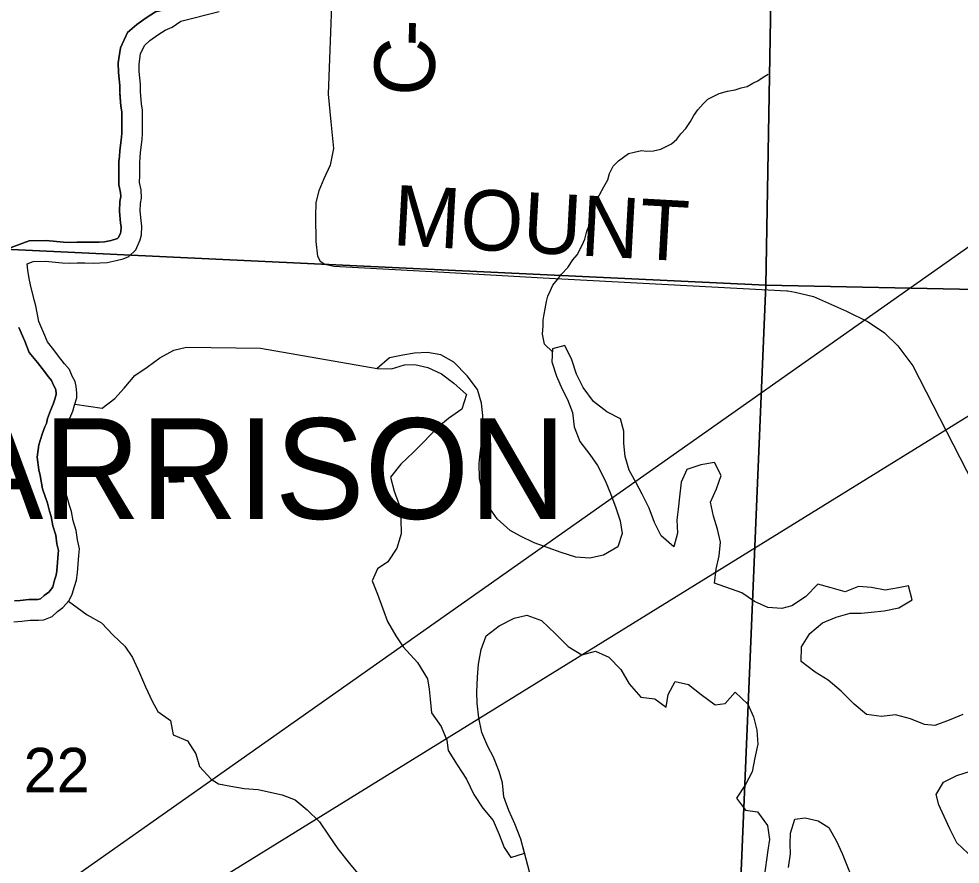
# Model space of a CAD drawing. Extents: x -7.5 to 26.5, y 3.5 to 25.5.
# Drawn here: x -1.65 to -0.763, y 21.515 to 22.311 of the extents above; entities that cross this region are included whole.
import ezdxf

# ---------------------------------------------------------------- set-up
doc = ezdxf.new("R2010")
doc.units = 0
for name, color, linetype in [('GM_X_Corporation', 7, 'Continuous'), ('GM_X_Corporation_Text', 7, 'Continuous'), ('GM_X_County_Road', 7, 'Continuous'), ('GM_X_County_Road_Text', 7, 'Continuous'), ('GM_X_Major_Lake', 7, 'Continuous'), ('GM_X_Minor_River', 7, 'Continuous'), ('GM_X_Minor_River_Text', 7, 'Continuous'), ('GM_X_Section_Text', 7, 'Continuous'), ('SH_Text', 7, 'Continuous')]:
    doc.layers.add(name, color=color, linetype=linetype)

msp = doc.modelspace()

# ---------------------------------------------------------------- linework, layer by layer
at = {"layer": 'GM_X_Corporation'}
for points in [[(-2.19987, 23.10777), (-0.9286, 23.08067), (-0.92908, 23.04507), (-0.94612, 22.06009), (-2.24786, 22.12167)], [(0.06885, 23.0315), (-0.1108, 22.04288), (-0.94612, 22.06009), (-0.92908, 23.04507)], [(-2.24786, 22.12167), (-0.94612, 22.06009), (-0.97818, 21.29975), (-1.02673, 21.30097), (-1.03065, 21.12371), (-1.27976, 21.1309), (-2.268, 21.16183)], [(-0.94612, 22.06009), (-0.1108, 22.04288), (-0.27046, 21.10184), (-1.03065, 21.12371), (-1.02673, 21.30097), (-0.97818, 21.29975)]]:
    msp.add_lwpolyline(points, close=True, dxfattribs=at)
at = {"layer": 'GM_X_County_Road'}
for points in [[(-1.36643, 22.41163), (-1.3634, 22.40775), (-1.35732, 22.39506), (-1.35357, 22.37755), (-1.35375, 22.35378), (-1.35509, 22.3235), (-1.35696, 22.27337), (-1.35822, 22.24014), (-1.35589, 22.21405), (-1.35339, 22.18903), (-1.35625, 22.17331), (-1.36247, 22.16029), (-1.36697, 22.14901), (-1.36983, 22.13811), (-1.37028, 22.12488), (-1.36999, 22.10143), (-1.36835, 22.08769), (-1.36566, 22.08289), (-1.36134, 22.0799), (-1.35279, 22.07828), (-1.255, 22.07295), (-1.15576, 22.06718)], [(-1.15576, 22.06718), (-0.92646, 22.05502), (-0.92548, 22.05486)], [(-0.92548, 22.05486), (-0.91856, 22.05377), (-0.90126, 22.04943), (-0.87009, 22.03576), (-0.84968, 22.02563), (-0.83441, 22.01534), (-0.82198, 22.00326), (-0.80778, 21.98427), (-0.75735, 21.88573), (-0.74688, 21.86603), (-0.73747, 21.84934), (-0.72504, 21.83282), (-0.71555, 21.82333), (-0.70312, 21.81294), (-0.69193, 21.80548), (-0.67968, 21.79883), (-0.66574, 21.79181), (-0.64586, 21.78187), (-0.62793, 21.77672), (-0.60645, 21.77495), (-0.59437, 21.77548)]]:
    msp.add_lwpolyline(points, dxfattribs=at)
at = {"layer": 'GM_X_Major_Lake'}
for points in [[(-0.91257, 21.7196), (-0.90469, 21.73235), (-0.89269, 21.74235), (-0.88003, 21.74777), (-0.86666, 21.75127), (-0.85641, 21.75142), (-0.84689, 21.75234), (-0.83471, 21.75359), (-0.82098, 21.75632), (-0.80828, 21.76402), (-0.81178, 21.77703), (-0.82131, 21.77534), (-0.83389, 21.77296), (-0.84675, 21.77553), (-0.85888, 21.77657), (-0.87152, 21.77153), (-0.88473, 21.77525), (-0.89718, 21.77857), (-0.90884, 21.76667), (-0.92157, 21.75821), (-0.93112, 21.75577), (-0.94438, 21.75683), (-0.95678, 21.76243), (-0.96875, 21.77068), (-0.99437, 21.77963), (-0.99293, 21.79291), (-0.98999, 21.80539), (-0.98894, 21.81829), (-0.9917, 21.83052), (-0.9956, 21.84278), (-0.99834, 21.85577), (-0.99273, 21.86857), (-0.98827, 21.88102), (-0.99445, 21.89333), (-1.00741, 21.89096), (-1.02042, 21.88669), (-1.02601, 21.87465), (-1.02746, 21.86099), (-1.02887, 21.84924), (-1.02985, 21.83937), (-1.02937, 21.82681), (-1.0327, 21.81396), (-1.04462, 21.82411), (-1.05117, 21.83681), (-1.05618, 21.85023), (-1.06272, 21.86331), (-1.06817, 21.87408), (-1.07474, 21.88602), (-1.07862, 21.89903), (-1.07986, 21.91123), (-1.07998, 21.92264), (-1.08313, 21.9345), (-1.0959, 21.94087), (-1.10859, 21.95066), (-1.11816, 21.96381), (-1.12433, 21.97649), (-1.12896, 21.98991), (-1.13549, 22.00336), (-1.14696, 22.0002), (-1.14761, 21.98805), (-1.14336, 21.97464), (-1.13794, 21.96235), (-1.13284, 21.95273), (-1.12819, 21.94046), (-1.1266, 21.92673), (-1.12121, 21.91292), (-1.11199, 21.90092), (-1.10464, 21.89049), (-1.09736, 21.87626), (-1.09233, 21.86398), (-1.08731, 21.85056), (-1.08341, 21.8383), (-1.08141, 21.82646), (-1.08548, 21.81401), (-1.09896, 21.80595), (-1.11193, 21.8032), (-1.1252, 21.80426), (-1.13877, 21.80837), (-1.1512, 21.81283), (-1.16438, 21.81769), (-1.17715, 21.82406), (-1.18691, 21.82923), (-1.19919, 21.84015), (-1.20802, 21.8529), (-1.21305, 21.86518), (-1.2158, 21.87817), (-1.21623, 21.89225), (-1.21526, 21.90174), (-1.21391, 21.91121), (-1.21285, 21.9245), (-1.21255, 21.93742), (-1.2138, 21.94924), (-1.2177, 21.96187), (-1.22727, 21.97502), (-1.23989, 21.98785), (-1.25227, 21.9946), (-1.26475, 21.99678), (-1.27691, 21.99629), (-1.28797, 21.99426), (-1.30056, 21.99188), (-1.31218, 21.98188)], [(-1.31218, 21.98188), (-1.29851, 21.98157), (-1.28628, 21.9851), (-1.27678, 21.98564), (-1.26431, 21.9827), (-1.25154, 21.97671), (-1.23996, 21.96808), (-1.22806, 21.95716), (-1.23254, 21.94358), (-1.24489, 21.93473), (-1.2565, 21.9251), (-1.26817, 21.91282), (-1.27788, 21.90315), (-1.28992, 21.89164), (-1.29969, 21.87931), (-1.29619, 21.8663), (-1.29155, 21.85327), (-1.28995, 21.83992), (-1.2895, 21.82622), (-1.29361, 21.81263), (-1.30225, 21.79989), (-1.31189, 21.79327), (-1.3167, 21.78197), (-1.31168, 21.76931), (-1.30704, 21.75627), (-1.30239, 21.74362), (-1.29472, 21.73013), (-1.28774, 21.71971), (-1.27402, 21.70495), (-1.26488, 21.68954), (-1.2632, 21.67999), (-1.26227, 21.67046), (-1.26105, 21.65751), (-1.25184, 21.64475), (-1.24644, 21.6317), (-1.24514, 21.62217), (-1.23671, 21.60867), (-1.2279, 21.59516), (-1.22102, 21.58055), (-1.21258, 21.56781), (-1.20297, 21.55619), (-1.19719, 21.54313), (-1.19253, 21.53086), (-1.18629, 21.52121), (-1.17328, 21.52548), (-1.17679, 21.53849), (-1.18253, 21.55306), (-1.18832, 21.56574), (-1.19297, 21.5784), (-1.19419, 21.59173), (-1.19736, 21.60245), (-1.20275, 21.61588), (-1.20784, 21.62588), (-1.21362, 21.63894), (-1.21635, 21.6527), (-1.21793, 21.6668), (-1.21845, 21.67708), (-1.21776, 21.69113), (-1.21672, 21.70328), (-1.21413, 21.71729), (-1.20966, 21.73012), (-1.1973, 21.73934), (-1.18308, 21.74663), (-1.17125, 21.7494), (-1.15731, 21.74452), (-1.1443, 21.73206), (-1.13242, 21.72), (-1.11931, 21.7121), (-1.1067, 21.71562), (-1.09392, 21.71001), (-1.08279, 21.69835), (-1.07474, 21.68486), (-1.06401, 21.67245), (-1.05076, 21.67063)], [(-0.7606, 21.65609), (-0.77363, 21.65068), (-0.78704, 21.64566), (-0.79689, 21.64664), (-0.81006, 21.65188), (-0.82402, 21.65562), (-0.83735, 21.65402), (-0.85136, 21.65586), (-0.86291, 21.66563), (-0.87516, 21.67807), (-0.88746, 21.68823), (-0.89982, 21.69574), (-0.91288, 21.70592), (-0.91257, 21.7196)], [(-1.05076, 21.67063), (-1.03993, 21.66278), (-1.03813, 21.67491), (-1.03141, 21.68692), (-1.01893, 21.68436), (-1.00699, 21.67496), (-0.99392, 21.66516), (-0.9844, 21.66647), (-0.97505, 21.6769), (-0.96316, 21.66561), (-0.95773, 21.6537), (-0.9546, 21.64108), (-0.95375, 21.62813), (-0.9567, 21.61527), (-0.9589, 21.60201), (-0.96525, 21.58999), (-0.97389, 21.57725), (-0.96541, 21.56603), (-0.95406, 21.56426), (-0.94448, 21.55149), (-0.94288, 21.53814), (-0.94424, 21.52829), (-0.94785, 21.50327)], [(-0.75559, 21.52517), (-0.76637, 21.5353), (-0.77291, 21.54838), (-0.77834, 21.55991), (-0.78341, 21.57105), (-0.78585, 21.58061), (-0.77875, 21.59224), (-0.76646, 21.59842), (-0.75345, 21.60269)], [(-0.92487, 21.51188), (-0.92306, 21.52477), (-0.92322, 21.53428), (-0.923, 21.54416), (-0.9189, 21.55738), (-0.909, 21.55867), (-0.89691, 21.55574), (-0.88681, 21.54943), (-0.8795, 21.53671), (-0.87445, 21.52519), (-0.87048, 21.5156), (-0.86508, 21.50255)]]:
    msp.add_lwpolyline(points, dxfattribs=at)
at = {"layer": 'GM_X_Minor_River'}
for points in [[(-1.46816, 22.33008), (-1.52088, 22.3176), (-1.52975, 22.31209), (-1.53838, 22.30571), (-1.54719, 22.2981), (-1.55382, 22.28387), (-1.55592, 22.26956), (-1.55569, 22.26038), (-1.55453, 22.2482), (-1.55436, 22.24161)], [(-1.55437, 22.24204), (-1.55453, 22.2482), (-1.55569, 22.26038), (-1.55592, 22.26956), (-1.55382, 22.28387), (-1.54719, 22.2981), (-1.53838, 22.30571), (-1.52975, 22.31209), (-1.52088, 22.3176), (-1.46816, 22.33008)], [(-1.53487, 22.24253), (-1.53504, 22.24937), (-1.5362, 22.26155), (-1.53637, 22.26839), (-1.53494, 22.27821), (-1.53127, 22.28607), (-1.52619, 22.29047), (-1.51879, 22.29593), (-1.51181, 22.30027), (-1.50526, 22.3031), (-1.49709, 22.30892), (-1.46105, 22.318)], [(-1.14711, 21.99736), (-1.15461, 22.00454), (-1.15634, 22.014), (-1.15582, 22.022), (-1.15572, 22.02733), (-1.15486, 22.03303), (-1.154, 22.03797), (-1.15274, 22.0448), (-1.15151, 22.04974), (-1.14913, 22.05465), (-1.14674, 22.06032), (-1.14246, 22.06559), (-1.13857, 22.07048), (-1.13274, 22.07686), (-1.12804, 22.08402), (-1.12376, 22.0889), (-1.11903, 22.09797), (-1.11664, 22.10364), (-1.1146, 22.11123), (-1.1126, 22.11653), (-1.11056, 22.12373), (-1.10895, 22.12866), (-1.10769, 22.1355), (-1.1057, 22.14004), (-1.10294, 22.14532), (-1.09861, 22.15287), (-1.09507, 22.15929), (-1.09344, 22.16536), (-1.08989, 22.17216), (-1.08484, 22.17741), (-1.07558, 22.18412), (-1.07023, 22.18556), (-1.06335, 22.18696), (-1.05841, 22.1865), (-1.05193, 22.18678), (-1.04506, 22.18819), (-1.03506, 22.19336), (-1.03003, 22.19785), (-1.02614, 22.20274), (-1.02148, 22.20762), (-1.01717, 22.21441), (-1.01402, 22.22007), (-1.01012, 22.22534), (-1.00507, 22.23097), (-1.0008, 22.23547), (-0.99004, 22.24063), (-0.98239, 22.24279), (-0.97513, 22.2442), (-0.96939, 22.24601), (-0.96365, 22.24744), (-0.95827, 22.2504), (-0.95366, 22.25261), (-0.94865, 22.25596), (-0.94403, 22.25893)], [(-1.55436, 22.24161), (-1.55347, 22.22892), (-1.55259, 22.2233), (-1.55248, 22.21753), (-1.55268, 22.21072), (-1.55255, 22.2035), (-1.55296, 22.19974), (-1.55347, 22.19472), (-1.55454, 22.18684), (-1.5547, 22.18164), (-1.55526, 22.17641), (-1.55523, 22.16389), (-1.55551, 22.15471), (-1.5537, 22.14735), (-1.55363, 22.1438), (-1.55446, 22.139), (-1.55475, 22.12957), (-1.55375, 22.11905), (-1.55329, 22.11493), (-1.55342, 22.11058), (-1.55375, 22.1093), (-1.55563, 22.105), (-1.55663, 22.10407), (-1.55744, 22.10375), (-1.56266, 22.10239), (-1.56891, 22.1009), (-1.57377, 22.10078), (-1.57933, 22.1006), (-1.58722, 22.10085), (-1.595, 22.10068), (-1.60134, 22.10053), (-1.60734, 22.10071), (-1.62392, 22.10242), (-1.63977, 22.10185), (-1.66263, 22.09355)], [(-1.66263, 22.09355), (-1.63977, 22.10185), (-1.62392, 22.10242), (-1.60734, 22.10071), (-1.60134, 22.10053), (-1.595, 22.10068), (-1.58722, 22.10085), (-1.57933, 22.1006), (-1.57377, 22.10078), (-1.56891, 22.1009), (-1.56266, 22.10239), (-1.55744, 22.10375), (-1.55663, 22.10407), (-1.55563, 22.105), (-1.55375, 22.1093), (-1.55342, 22.11058), (-1.55329, 22.11493), (-1.55375, 22.11905), (-1.55475, 22.12957), (-1.55446, 22.139), (-1.55363, 22.1438), (-1.5537, 22.14735), (-1.55551, 22.15471), (-1.55523, 22.16389), (-1.55526, 22.17641), (-1.5547, 22.18164), (-1.55454, 22.18684), (-1.55347, 22.19472), (-1.55296, 22.19974), (-1.55255, 22.2035), (-1.55268, 22.21072), (-1.55248, 22.21753), (-1.55259, 22.2233), (-1.55347, 22.22892), (-1.55433, 22.24117)], [(-1.65423, 21.74333), (-1.6466, 21.74386), (-1.63896, 21.74476), (-1.63096, 21.74489), (-1.626, 21.74512), (-1.61829, 21.74829), (-1.6132, 21.75307), (-1.60814, 21.75671), (-1.60223, 21.76336), (-1.59939, 21.76934), (-1.59727, 21.77649), (-1.59518, 21.78249), (-1.59422, 21.7893), (-1.59359, 21.79763), (-1.59297, 21.80558), (-1.59239, 21.81201), (-1.59442, 21.82042), (-1.59568, 21.8292), (-1.59845, 21.83839), (-1.60009, 21.84717), (-1.60181, 21.85292), (-1.60387, 21.86057), (-1.60631, 21.86786), (-1.60842, 21.87362), (-1.61037, 21.88468), (-1.61137, 21.88965), (-1.61263, 21.89842), (-1.61165, 21.9056), (-1.60913, 21.91349), (-1.60705, 21.91912), (-1.60462, 21.92398), (-1.60369, 21.92964), (-1.60163, 21.93489), (-1.59876, 21.94164), (-1.59707, 21.94728), (-1.59496, 21.95404), (-1.59481, 21.95897), (-1.5954, 21.96468), (-1.59639, 21.96965), (-1.59929, 21.97467), (-1.60177, 21.98082), (-1.60655, 21.98629), (-1.61205, 21.99329), (-1.61643, 21.9995), (-1.62268, 22.0069), (-1.62586, 22.01497), (-1.63085, 22.02613), (-1.63346, 22.04064), (-1.63519, 22.04638), (-1.63857, 22.06053), (-1.63991, 22.06664), (-1.6412, 22.07428), (-1.64178, 22.08037), (-1.63601, 22.08247), (-1.62457, 22.08287), (-1.60864, 22.08124), (-1.60141, 22.08101), (-1.59455, 22.08118), (-1.58731, 22.08133), (-1.57933, 22.08109), (-1.57323, 22.08128), (-1.56638, 22.08144), (-1.55794, 22.08346), (-1.55142, 22.08516), (-1.54602, 22.08727), (-1.53936, 22.09351), (-1.53527, 22.10287), (-1.53398, 22.10777), (-1.53374, 22.11573), (-1.53434, 22.12106), (-1.53521, 22.1302), (-1.53501, 22.13702), (-1.53409, 22.14231), (-1.53424, 22.14991), (-1.53593, 22.15679), (-1.53573, 22.16361), (-1.53575, 22.17538), (-1.53522, 22.1803), (-1.53508, 22.18523), (-1.5341, 22.19241), (-1.53356, 22.19771), (-1.53303, 22.20263), (-1.53317, 22.2106), (-1.53296, 22.21742), (-1.53311, 22.22502), (-1.53407, 22.23112), (-1.53487, 22.24253)], [(-1.64963, 22.02034), (-1.64384, 22.0074), (-1.63965, 21.99676), (-1.63188, 21.98756), (-1.6277, 21.98163), (-1.62157, 21.97382), (-1.61862, 21.97046), (-1.61687, 21.96611), (-1.61489, 21.96268), (-1.61471, 21.96177), (-1.61435, 21.95826), (-1.61438, 21.9573), (-1.61572, 21.95298), (-1.61713, 21.94828), (-1.61969, 21.94228), (-1.6226, 21.93485), (-1.62339, 21.93006), (-1.62498, 21.92688), (-1.62758, 21.91984), (-1.63075, 21.90992), (-1.63232, 21.89835), (-1.6306, 21.88635), (-1.62955, 21.88108), (-1.62734, 21.86853), (-1.62472, 21.8614), (-1.62255, 21.85493), (-1.62058, 21.84758), (-1.61907, 21.84256), (-1.61743, 21.83377), (-1.61478, 21.82497), (-1.6136, 21.81674), (-1.6121, 21.81055), (-1.61241, 21.80721), (-1.61304, 21.79912), (-1.61362, 21.79141), (-1.61423, 21.7871), (-1.61584, 21.78246), (-1.61766, 21.77634), (-1.61866, 21.77424), (-1.62128, 21.77128), (-1.62562, 21.76817), (-1.62903, 21.76497), (-1.63029, 21.76445), (-1.63157, 21.76439), (-1.64027, 21.76425), (-1.64841, 21.76329), (-1.65371, 21.76292)], [(-1.65371, 21.76292), (-1.64841, 21.76329), (-1.64027, 21.76425), (-1.63157, 21.76439), (-1.63029, 21.76445), (-1.62903, 21.76497), (-1.62562, 21.76817), (-1.62128, 21.77128), (-1.61866, 21.77424), (-1.61766, 21.77634), (-1.61584, 21.78246), (-1.61423, 21.7871), (-1.61362, 21.79141), (-1.61304, 21.79912), (-1.61241, 21.80721), (-1.6121, 21.81055), (-1.6136, 21.81674), (-1.61478, 21.82497), (-1.61743, 21.83377), (-1.61907, 21.84256), (-1.62058, 21.84758), (-1.62255, 21.85493), (-1.62472, 21.8614), (-1.62734, 21.86853), (-1.62955, 21.88108), (-1.6306, 21.88635), (-1.63232, 21.89835), (-1.63075, 21.90992), (-1.62758, 21.91984), (-1.62498, 21.92688), (-1.62339, 21.93006), (-1.6226, 21.93485), (-1.61969, 21.94228), (-1.61713, 21.94828), (-1.61572, 21.95298), (-1.61438, 21.9573), (-1.61435, 21.95826), (-1.61471, 21.96177), (-1.61489, 21.96268), (-1.61687, 21.96611), (-1.61862, 21.97046), (-1.62157, 21.97382), (-1.6277, 21.98163), (-1.63188, 21.98756), (-1.63965, 21.99676), (-1.64384, 22.0074), (-1.64963, 22.02034)], [(-1.59674, 21.94831), (-1.57099, 21.94439), (-1.559, 21.9536), (-1.55042, 21.96328), (-1.54026, 21.9752), (-1.52869, 21.9829), (-1.51671, 21.99174), (-1.50363, 21.99903), (-1.4918, 22.00178), (-1.42193, 22.00092), (-1.31218, 21.98188)], [(-1.60287, 21.76264), (-1.58515, 21.74975), (-1.57167, 21.74221), (-1.56056, 21.73054), (-1.5498, 21.7204), (-1.54246, 21.70959), (-1.53597, 21.69537), (-1.53022, 21.68193), (-1.52409, 21.66848), (-1.51863, 21.65885), (-1.50669, 21.6502), (-1.50436, 21.63684), (-1.49083, 21.6312), (-1.48277, 21.61884), (-1.47927, 21.60698), (-1.46855, 21.59494)], [(-1.46855, 21.59494), (-1.46161, 21.59081), (-1.44988, 21.5886), (-1.43741, 21.58637), (-1.42414, 21.58526), (-1.41432, 21.5831), (-1.40147, 21.58048), (-1.38944, 21.5756), (-1.37791, 21.56617), (-1.36643, 21.55483), (-1.35802, 21.54244), (-1.34924, 21.52965), (-1.33821, 21.51567), (-1.32753, 21.50284), (-1.31607, 21.49112), (-1.30336, 21.48318), (-1.29105, 21.47449), (-1.28458, 21.46062), (-1.2818, 21.45066), (-1.2757, 21.43718), (-1.26496, 21.42663), (-1.25228, 21.41755), (-1.2327, 21.39458)], [(-1.06741, 21.29548), (-1.07227, 21.30797), (-1.07464, 21.32057), (-1.07357, 21.33424), (-1.0737, 21.34527), (-1.07567, 21.359), (-1.07883, 21.37048), (-1.0823, 21.38463), (-1.0855, 21.39459), (-1.09133, 21.40537), (-1.09867, 21.41656), (-1.11053, 21.42938), (-1.12387, 21.44375), (-1.13572, 21.45732), (-1.14643, 21.47049), (-1.1579, 21.48368), (-1.1656, 21.49602), (-1.17499, 21.53181)]]:
    msp.add_lwpolyline(points, dxfattribs=at)
at = {"layer": 'SH_Text'}
msp.add_lwpolyline([(2.44493, 24.35104), (-2.59609, 20.79948), (2.44493, 23.91629)], close=True, dxfattribs=at)

# ---------------------------------------------------------------- texts
at = {"layer": 'GM_X_Corporation_Text'}
msp.add_text('HARRISON', height=0.094697, rotation=0.00001, dxfattribs=at).set_placement((-1.80241, 21.84022))
at = {"layer": 'GM_X_County_Road_Text'}
for s, height, rotation, p in [('-', 0.05682, 88.76355, (-1.25742, 22.2846)), ('C', 0.05682, 88.69431, (-1.25849, 22.23787)), ('MOUNT', 0.056818, 356.83039, (-1.29834, 22.09801))]:
    msp.add_text(s, height=height, rotation=rotation, dxfattribs=at).set_placement(p)
at = {"layer": 'GM_X_Minor_River_Text'}
msp.add_text('.', height=0.0947, rotation=92.12886, dxfattribs=at).set_placement((-1.49335, 21.86313))
at = {"layer": 'GM_X_Section_Text'}
msp.add_text('22', height=0.041856, rotation=0.00001, dxfattribs=at).set_placement((-1.64508, 21.58271))

doc.saveas('drawing.dxf')
